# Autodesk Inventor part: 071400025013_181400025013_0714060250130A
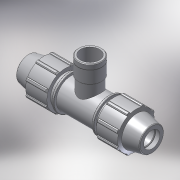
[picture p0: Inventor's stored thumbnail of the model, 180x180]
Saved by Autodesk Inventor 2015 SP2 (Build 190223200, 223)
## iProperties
Created: 2017-02
Part Number: 071400025013_181400025013_0714060250130A
Material: PVC-Piping
Description: PLASSON TEE WITH THREADED FEMALE OFFTAKE 25-1.1/4"-25
Document SubType Name: Modeling
Designer: KIM
Mass: 92.6774 g
Surface Area: 199.44 cm^2
Volume: 66.1981 cm^3
Density: 1.4 g/cm^3
Appearance: Smooth - White
Author: KIM
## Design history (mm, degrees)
derived "07140.ipt"
feature "Solid1::07140.ipt"
feature "Solid2::07140.ipt"
tag "TaggingFeature1"
body "Solid1"
other parameters: "d2" = 25, "d4" = 6.58333, "d5" = 18.96, "d7" = 54, "d11" = 2.63333, "d13" = 120 deg, "d14" = 37.5, "d15" = 12 deg, "d16" = 46.98, "d18" = 1.25, "d19" = 35 deg, "d20" = 17.5 deg, "d21" = 50.22, "d23" = 0, "d25" = 360 deg, "d27" = 1.08, "d33" = 0.5, "d42" = 28.44, "d43" = 1.62, "d46" = 0.75, "d68" = 4.74, "d72" = 64, "d76" = 38.952, "d80" = 1.16856, "d91" = 40.5, "d93" = 58, "d95" = 22.5, "d112" = 25, "d115" = 48.69, "d116" = 135 deg, "d117" = 44.7948, "d118" = 158, "d119" = 22.5, "d121" = 0, "d122" = 22.5, "d124" = 0, "d128" = 0, "d129" = 2.5, "d130" = 7.5, "d131" = 0.3, "d132" = 0.3, "d133" = 48.69, "d_" = 25, "E_" = 54, "A_" = 64, "l_" = 58, "l_2" = 25, "Rp_" = 38.952, "H_" = 158
